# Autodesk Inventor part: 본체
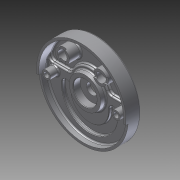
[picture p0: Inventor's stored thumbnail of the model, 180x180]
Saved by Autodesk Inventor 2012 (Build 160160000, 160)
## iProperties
Created: 2015-04
Part Number: 본체
Material: Default
Document SubType Name: Modeling
Designer: Owner
Density: 1 g/cm^3
Author: Owner
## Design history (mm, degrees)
sketch "스케치1"
  geometry: C1 r 95 at (0, 0); 1 further point
  constraints: 1 centre point, 1 coincident
  dimensions: "d0" = 190 diameter of C1
extrude "돌출1" new body sketch "스케치1" distance "d1" = 27; taper "d2" = 0 deg
sketch "스케치2"
  geometry: L1 (-95, 0)-(95, 0); L2 (-94.638, -8.28)-(-89.658, -7.844); L3 (89.658, -7.844)-(94.638, -8.28); A1 r 95 centre (0, 0) between (-95, 0) and (95, 0) reference; A2 r 95 centre (0, 0) between (94.638, -8.28) and (-94.638, -8.28); A3 r 90 centre (0, 0) between (89.658, -7.844) and (-89.658, -7.844); 1 further point
  constraints: 10 point on circle, 6 end point, 3 coincident, 2 centre point, 1 concentric, 1 horizontal, 1 midpoint
  dimensions: "d3" = 180 diameter of A3; "d6" = 5 deg angle of L1 L2; "d8" = 5 deg angle of L1 L3; "d9" = 16.49658 distance from line of L3.end L2; "d10" = 15.62834 distance from line of L3.start L2
extrude "돌출2" join sketch "스케치2" distance "d11" = 5; taper "d12" = 0 deg
sketch "스케치3"
  geometry: C1 r 90 at (0, 0); A1 r 95 centre (0, 0) between (-94.638, -8.28) and (94.638, -8.28) reference
  constraints: 1 centre point, 1 coincident
  dimensions: "d13" = 180 diameter of C1
extrude "돌출3" cut sketch "스케치3" distance "d14" = 20; taper "d15" = 0 deg
sketch "스케치4"
  geometry: L1 (-89.196, 12)-(89.196, 12); C1 r 42 at (0, 0); A1 r 90 centre (0, 0) between (-89.196, 12) and (89.196, 12) reference
  constraints: 2 end point, 2 point on circle, 1 centre point, 1 coincident, 1 horizontal
  dimensions: "d16" = 84 diameter of C1; "d17" = 12 distance from line of L1 C1.centre
extrude "돌출4" join sketch "스케치4" distance "d18" = 7; taper "d19" = 0 deg
fillet "모깎기1" dims "d20" = 10
sketch "스케치5"
  geometry: L1 (-90, 14)-(24.75, 14) reference; L2 (90, 32)-(-7.844, 32) reference; L3 (35, 14)-(33.237, 24); L4 (33.237, 24)-(0, 24); L5 (0, 14)-(0, 24); L6 (17.769, 14)-(42, 14) reference; L7 (0, 14)-(35, 14); 1 further point
  constraints: 8 end point, 2 point on line, 1 collinear, 1 parallel, 1 vertical, 1 vertical alignment
  dimensions: "d21" = 35 distance of L3.start L5.start; "d22" = 10 distance between parallel lines of L4 L1; "d23" = 100 deg angle of L6 L3
revolve "회전1" sketch "스케치5" stored, may be unused: angle "d24" = 90 deg
hole "구멍1" diameter "d27" = 23; stored, may be unused: countersink angle "d31" = 90 deg, drill point angle "d33" = 118 deg; dims "d25" = 10, "d26" = 10, "d28" = 6, "d29" = 50, "d30" = 15, "d32" = 8
sketch "스케치6"
  geometry: C1 r 15 at (-40, 52); C2 r 15 at (40, 52); A1 r 90 centre (0, 0) between (86.53, 24.75) and (-86.53, 24.75) reference
  constraints: 2 centre point, 1 horizontal alignment
  dimensions: "d34" = 30 diameter of C1; "d35" = 30 diameter of C2; "d36" = 80 distance of C1.centre C2.centre; "d37" = 40 horizontal distance of C1.centre A1.centre; "d38" = 52 vertical distance of C1.centre A1.centre
extrude "돌출5" join sketch "스케치6" distance "d39" = 25; taper "d40" = 0 deg
hole "구멍2" diameter "d43" = 20; stored, may be unused: countersink angle "d47" = 90 deg, drill point angle "d49" = 118 deg; dims "d41" = 10, "d42" = 10, "d44" = 6, "d45" = 4, "d46" = 2, "d48" = 8
hole "구멍3" diameter "d52" = 20; stored, may be unused: countersink angle "d56" = 90 deg, drill point angle "d58" = 118 deg; dims "d50" = 10, "d51" = 10, "d53" = 6, "d54" = 4, "d55" = 2, "d57" = 8
sketch "스케치7"
  geometry: L1 (-6, 16.78)-(6, 16.78); L2 (6, 16.78)-(6, -16.78); L3 (6, -16.78)-(-6, -16.78); L4 (-6, -16.78)-(-6, 16.78); C1 r 10 at (0, 0) reference; 3 further points
  constraints: 8 end point, 2 midpoint, 2 parallel, 1 horizontal, 1 horizontal alignment, 1 perpendicular, 1 vertical alignment
  dimensions: "d59" = 12 distance of L1.start L1.end
extrude "돌출6" cut sketch "스케치7" distance "d60" = 3; taper "d61" = 0 deg
sketch "스케치8"
  geometry: L1 (-26.553, 6)-(26.553, 6); L2 (26.553, 6)-(26.553, -6); L3 (26.553, -6)-(-26.553, -6); L4 (-26.553, -6)-(-26.553, 6); C1 r 10 at (0, 0) reference; 3 further points
  constraints: 8 end point, 2 midpoint, 2 parallel, 1 horizontal, 1 horizontal alignment, 1 perpendicular, 1 vertical alignment
  dimensions: "d62" = 12 distance of L3.end L1.start
extrude "돌출7" cut sketch "스케치8" distance "d63" = 3; taper "d64" = 0 deg
sketch "스케치9"
  geometry: L1 (-76.916, 12)-(-47.117, 12) reference; L2 (47.117, 12)-(76.916, 12) reference; L3 (-59, -19)-(59, -19); L4 (-58.749, -14)-(58.749, -14); L5 (0, 0)-(0, -57.638); A1 r 35 centre (0, 0) between (34.911, 2.5) and (-34.911, 2.5) reference; A2 r 42 centre (0, 0) between (38.056, 17.769) and (-38.056, 17.769) reference; A3 r 50 centre (0, -19) between (-49.749, -14) and (49.749, -14); A4 r 9 centre (-49.749, -14) between (-58.749, -14) and (-58.704, -13.1); A5 r 9 centre (49.749, -14) between (58.749, -14) and (58.704, -13.1); A6 r 59 centre (0, -19) between (50.2, 12) and (-50.2, 12); A7 r 59 centre (0, -19) between (-58.704, -13.1) and (58.704, -13.1); A8 r 41 centre (0, -19) between (34.911, 2.5) and (-34.911, 2.5); A9 r 41 centre (0, -19) between (-40.794, -14.9) and (40.794, -14.9)
  constraints: 20 point on circle, 7 centre point, 6 end point, 5 point on line, 2 coincident, 2 parallel, 2 tangent, 1 midpoint, 1 vertical
  dimensions: "d68" = 19 distance from line of A1.centre L3; "d69" = 5 distance between parallel lines of L4 L3; "d76" = 18 diameter of A4; "d77" = 18 diameter of A5; "d78" = 59 radius of A7
extrude "돌출8" cut sketch "스케치9" distance "d79" = 7; taper "d80" = 0 deg
sketch "스케치10"
  geometry: L1 (47.117, 12)-(76.916, 12) reference; L2 (-74, 0)-(74, 0); C1 r 35 at (0, 0) reference; C2 r 9 at (-74, 0); C3 r 9 at (74, 0); A1 r 42 centre (0, 0) between (38.056, 17.769) and (-38.056, 17.769) reference; A2 r 74 centre (0, 0) between (-74, 0) and (74, 0); 1 further point
  constraints: 4 coincident, 3 centre point, 2 end point, 2 point on circle, 1 midpoint, 1 parallel
  dimensions: "d81" = 148 diameter of A2; "d82" = 18 diameter of C2; "d83" = 18 diameter of C3
extrude "돌출9" join sketch "스케치10" distance "d84" = 18; taper "d85" = 0 deg
hole "구멍4" diameter "d88" = 11; stored, may be unused: countersink angle "d92" = 90 deg, drill point angle "d94" = 118 deg; dims "d86" = 10, "d87" = 10, "d89" = 6, "d90" = 4, "d91" = 2, "d93" = 8
hole "구멍5" diameter "d97" = 11; stored, may be unused: countersink angle "d101" = 90 deg, drill point angle "d103" = 118 deg; dims "d95" = 10, "d96" = 10, "d98" = 6, "d99" = 4, "d100" = 2, "d102" = 8
hole "구멍6" diameter "d106" = 18; stored, may be unused: countersink angle "d110" = 90 deg, drill point angle "d112" = 0 deg; dims "d104" = 10, "d105" = 10, "d107" = 6, "d108" = 4, "d109" = 2, "d111" = 11
hole "구멍7" diameter "d115" = 18; stored, may be unused: countersink angle "d119" = 90 deg, drill point angle "d121" = 0 deg; dims "d113" = 10, "d114" = 10, "d116" = 6, "d117" = 4, "d118" = 2, "d120" = 11
sketch "스케치11"
  geometry: L1 (0, 0)-(0, -72); L2 (0, 0)-(8.132, -8.132); L3 (39.44, -39.44)-(47.244, -47.244); L4 (0, 0)-(-8.132, -8.132); L5 (-39.44, -39.44)-(-47.244, -47.244); C1 r 95 at (0, 0) reference; C2 r 68 at (0, 0); A1 r 11.5 centre (0, 0) between (8.132, -8.132) and (-8.132, -8.132) reference; A2 r 51 centre (0, 0) between (-32.699, -39.138) and (32.699, -39.138); A3 r 72 centre (0, 0) between (71.48, -8.64) and (-71.48, -8.64); A4 r 72 centre (0, 0) between (-46.97, -54.569) and (46.97, -54.569); A5 r 5 centre (35.904, -42.975) between (39.44, -39.44) and (32.699, -39.138); A6 r 5 centre (43.709, -50.78) between (46.97, -54.569) and (47.244, -47.244); A7 r 5 centre (-43.709, -50.78) between (-47.244, -47.244) and (-46.97, -54.569); A8 r 5 centre (-35.904, -42.975) between (-32.699, -39.138) and (-39.44, -39.44); 6 further points
  constraints: 21 point on circle, 10 end point, 8 centre point, 8 tangent, 4 point on line, 3 coincident, 3 equal radius, 1 vertical, 5 other
  dimensions: "d122" = 102 diameter of A2; "d126" = 72 radius of A4; "d127" = 45 deg angle of L5 L1; "d128" = 45 deg angle of L1 L3; "d129" = 72 distance from line of point (50.912, -50.912) L5; "d130" = 51 distance from line of point (36.062, -36.062) L5; "d131" = 5 radius of A5; "d133" = 136 diameter of C2
extrude "돌출10" join sketch "스케치11" distance "d134" = 5; taper "d135" = 0 deg
sketch "스케치12"
  geometry: C1 r 68 at (0, 0); A1 r 51 centre (0, 0) between (-32.699, -39.138) and (32.699, -39.138) reference
  constraints: 1 centre point, 1 coincident, 1 other
  dimensions: "d136" = 136 diameter of C1
feature "엠보싱1" sketch "스케치12" dims "d137" = 0.5, "d138" = 0
fillet "모깎기2" dims "d139" = 1
fillet "모깎기3" dims "d140" = 3
chamfer "모따기1" distance "d141" = 1; stored, may be unused: second distance "d142" = 2, angle "d143" = 45 deg
node "솔리드1"
other parameters: "d73" = 118, "d74" = 82, "d75" = 9, "d123" = 144, "d124" = 45 deg, "d125" = 45 deg
